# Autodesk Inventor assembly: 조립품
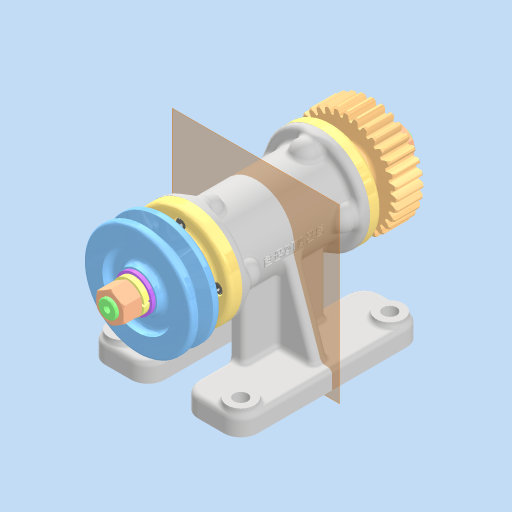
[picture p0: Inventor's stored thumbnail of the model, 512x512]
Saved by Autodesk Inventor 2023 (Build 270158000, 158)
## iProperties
Created: 2026-06
Part Number: 조립품
Document SubType Name: Assembly
Designer: home
Author: home
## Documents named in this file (18)
- C:\Users\home\Desktop\760603V1009\조립품.iam
- C:\Users\home\Desktop\760603V1009\본체.ipt
- C:\Users\home\Desktop\760603V1009\커버.ipt
- C:\Users\home\Desktop\760603V1009\6각 구멍붙이 볼트 M4x8.ipt
- C:\Users\home\Desktop\760603V1009\부품_MIR.ipt
- C:\Users\home\Desktop\760603V1009\커버_MIR.ipt
- C:\Users\home\Desktop\760603V1009\6각 구멍붙이 볼트 M4x8_MIR.ipt
- C:\Users\home\Desktop\760603V1009\깊은 홈 볼 베어링 6904.ipt
- C:\Users\home\Desktop\760603V1009\깊은 홈 볼 베어링 6904_MIR.ipt
- C:\Users\home\Desktop\760603V1009\축.ipt
- C:\Users\home\Desktop\760603V1009\오일 실 20 35 8.ipt
- C:\Users\home\Desktop\760603V1009\오일 실 20 35 8_MIR.ipt
- C:\Users\home\Desktop\760603V1009\V 벨트 풀리.ipt
- C:\Users\home\Desktop\760603V1009\평행 키 4x4x14.ipt
- C:\Users\home\Desktop\760603V1009\평 와셔 M12.ipt
- C:\Users\home\Desktop\760603V1009\스프링 와셔 M12.ipt
- C:\Users\home\Desktop\760603V1009\6각 너트 M12x1.ipt
- C:\Users\home\Desktop\760603V1009\스퍼 기어.ipt
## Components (11 placed, 4 different names)
1. 6각 구멍붙이 볼트 M4x8_MIR:1
2. 6각 구멍붙이 볼트 M4x8_MIR:2
3. 6각 구멍붙이 볼트 M4x8_MIR:3
4. 6각 구멍붙이 볼트 M4x8_MIR:4
5. V 벨트 풀리:1 — 각도:2
6. 6각 너트 M12x1:1
7. 6각 너트 M12x1:2
8. 6각 구멍붙이 볼트 M4x8:1
9. 6각 구멍붙이 볼트 M4x8:2
10. 6각 구멍붙이 볼트 M4x8:3
11. 6각 구멍붙이 볼트 M4x8:4
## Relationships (1: Angle 1)
- 각도:2 [Angle]: V 벨트 풀리:1
